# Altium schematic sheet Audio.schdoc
size 420 x 297 mm; Symbol: Drawing-Symbol_A4; Company: 嘉立创EDA; Version: V1.0; Page Size: A4; @Project Name: A113 Android MircroPhone; @Page Count: 7; @Update Date: 2025-12-04; @Create Date: 2025-12-04; @Schematic Name: Schematic1; @Page No: 6; @Page Name: Audio; @Create Time: 23:41:37; @Update Time: 23:41:46; Border: 1; Width: 1655; Height: 1170; Region Start: 1; X Region Count: 6; Y Region Count: 4; Blade Width: 10; Title Block Position: 3; @Board Name: Board1; Device: Drawing-Symbol_A4
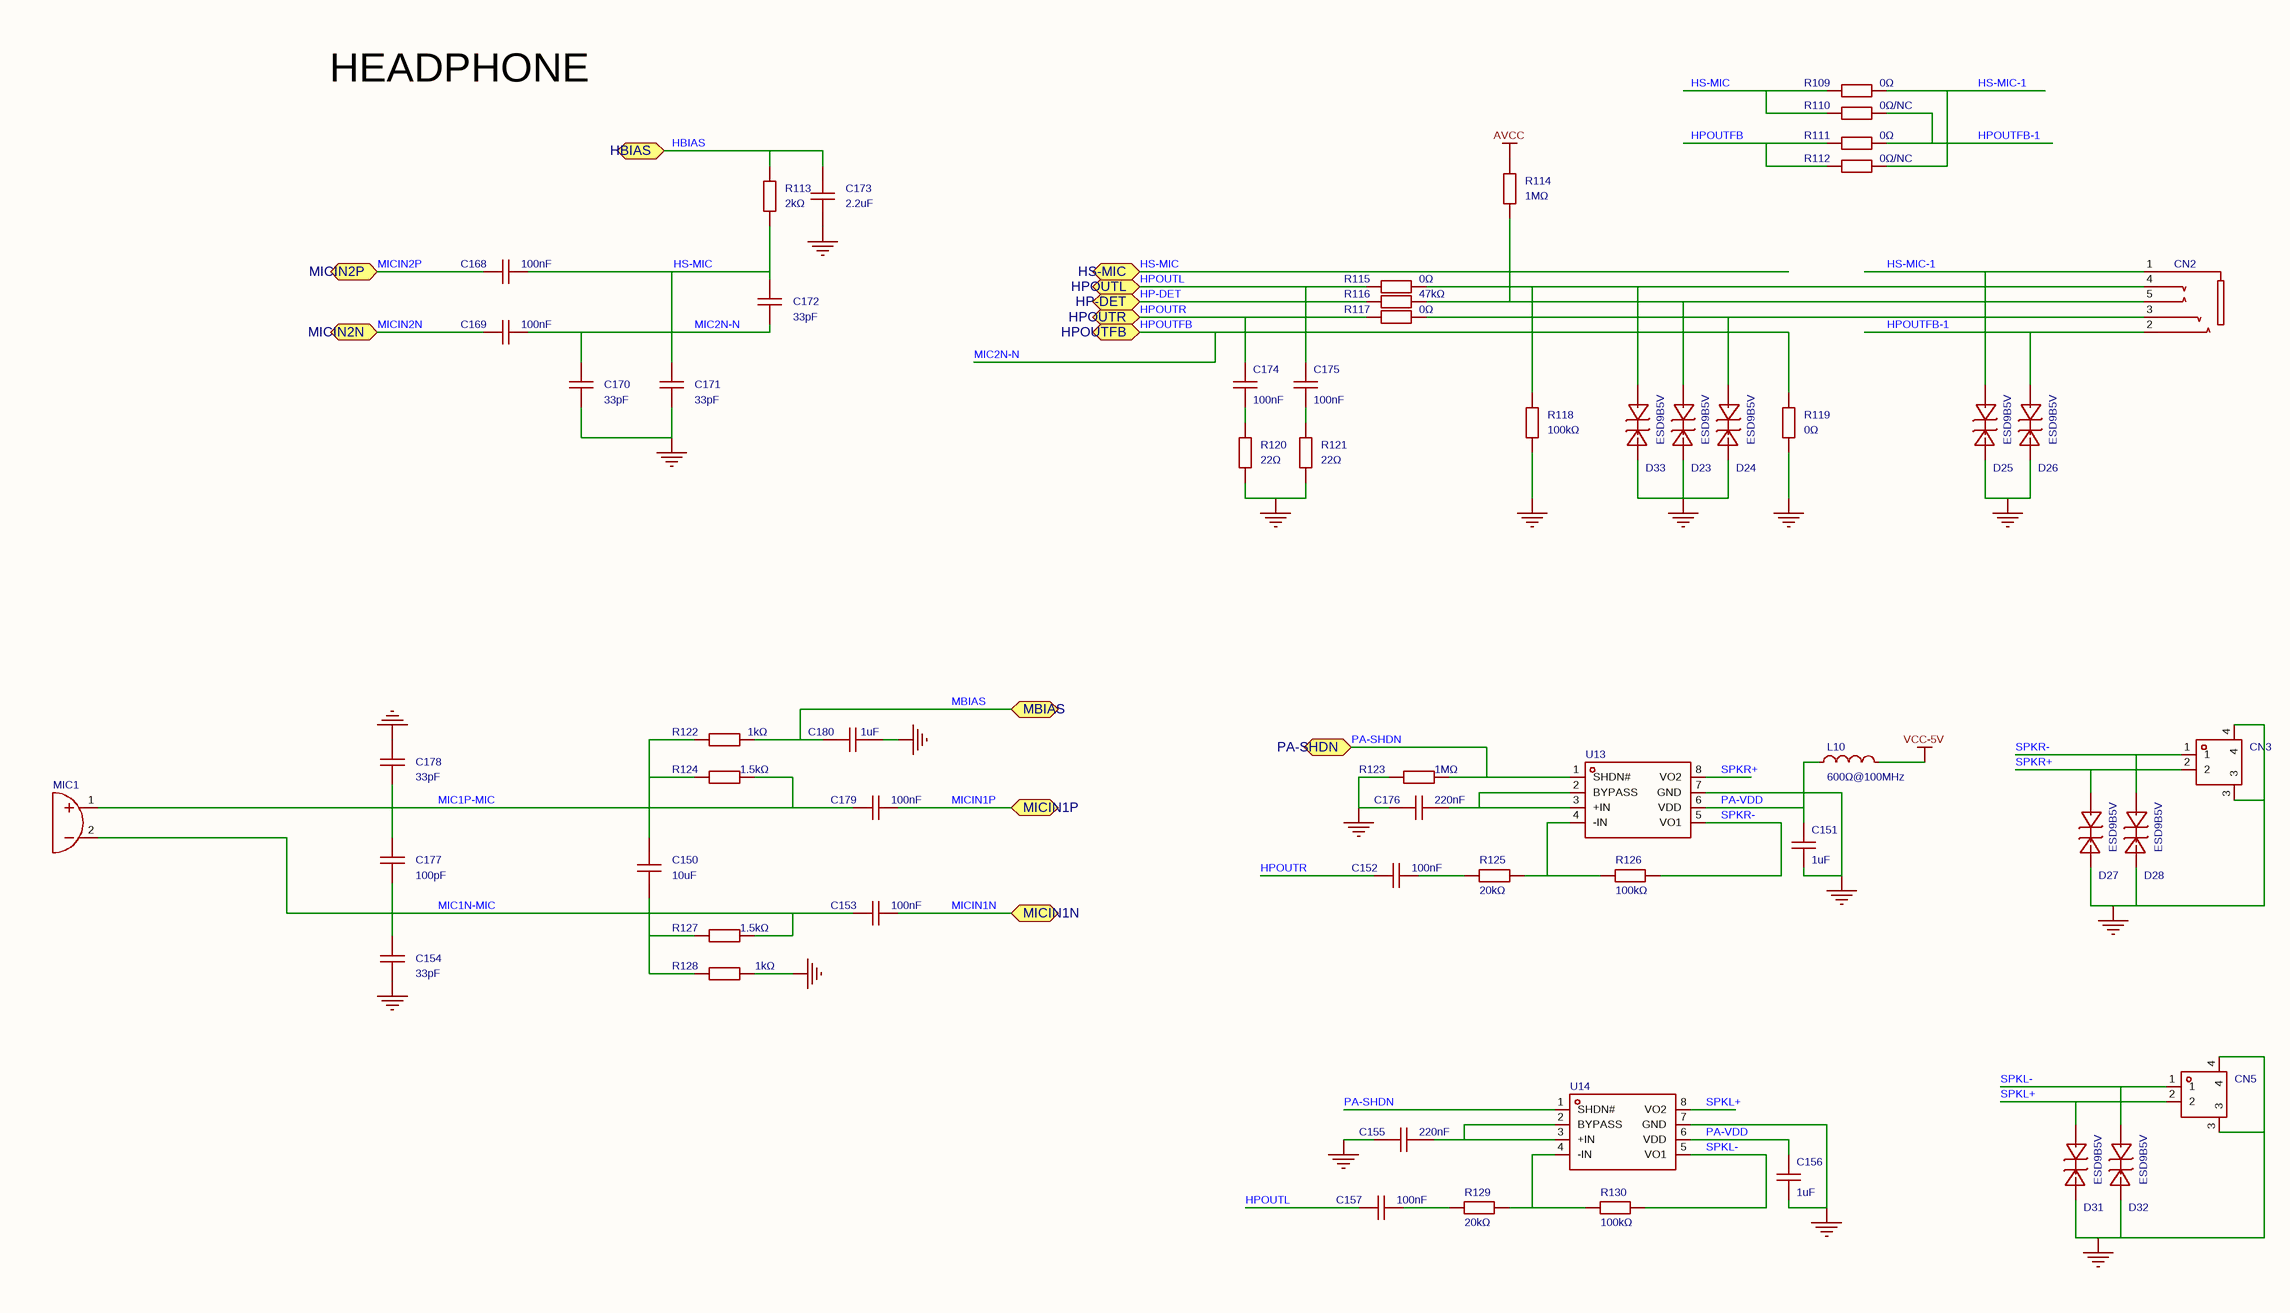
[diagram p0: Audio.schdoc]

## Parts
C150  10uF  [C0603]
C151  1uF  [C0402]
C152  100nF  [C0402]
C153  100nF  [C0402]
C154  33pF  [C0402]
C155  220nF  [C0402]
C156  1uF  [C0402]
C157  100nF  [C0402]
C168  100nF  [C0402]
C169  100nF  [C0402]
C170  33pF  [C0402]
C171  33pF  [C0402]
C172  33pF  [C0402]
C173  2.2uF  [C0402]
C174  100nF  [C0402]
C175  100nF  [C0402]
C176  220nF  [C0402]
C177  100pF  [C0402]
C178  33pF  [C0402]
C179  100nF  [C0402]
C180  1uF  [C0402]
CN2  ST-0277D00-052-142  [AUDIO-TH_ST-0277D00-052-142]  (value not drawn)
CN3  1.0-2PWB  [CONN-SMD_2P-P1.00_DEALON_1.0-2PWB]  (value not drawn)
CN5  1.0-2PWB  [CONN-SMD_2P-P1.00_DEALON_1.0-2PWB]  (value not drawn)
D23  ESD9B5V  [SOD-923_L0.8-W0.6-LS1.0-BI-1]
D24  ESD9B5V  [SOD-923_L0.8-W0.6-LS1.0-BI-1]
D25  ESD9B5V  [SOD-923_L0.8-W0.6-LS1.0-BI-1]
D26  ESD9B5V  [SOD-923_L0.8-W0.6-LS1.0-BI-1]
D27  ESD9B5V  [SOD-923_L0.8-W0.6-LS1.0-BI-1]
D28  ESD9B5V  [SOD-923_L0.8-W0.6-LS1.0-BI-1]
D31  ESD9B5V  [SOD-923_L0.8-W0.6-LS1.0-BI-1]
D32  ESD9B5V  [SOD-923_L0.8-W0.6-LS1.0-BI-1]
D33  ESD9B5V  [SOD-923_L0.8-W0.6-LS1.0-BI-1]
L10  Impedance @ Frequency: 600Ω@100MHz  [L0603]  (hidden comment: CBG160808U601T)
MIC1  GMI6027P-2C30DB  [MIC-TH_BD6.0-P1.90-D0.4-L]  (value not drawn)
R109  0Ω  [R0402]
R110  0Ω/NC  [R0402]
R111  0Ω  [R0402]
R112  0Ω/NC  [R0402]
R113  2kΩ  [R0402]
R114  1MΩ  [R0402]
R115  0Ω  [R0402]
R116  47kΩ  [R0402]
R117  0Ω  [R0402]
R118  100kΩ  [R0402]
R119  0Ω  [R0402]
R120  22Ω  [R0402]
R121  22Ω  [R0402]
R122  1kΩ  [R0402]
R123  1MΩ  [R0402]
R124  1.5kΩ  [R0402]
R125  20kΩ  [R0402]
R126  100kΩ  [R0402]
R127  1.5kΩ  [R0402]
R128  1kΩ  [R0402]
R129  20kΩ  [R0402]
R130  100kΩ  [R0402]
U13  LPA4890MSF  [MSOP-8_L3.0-W3.0-P0.65-LS5.0-BL]  (value not drawn)
U14  LPA4890MSF  [MSOP-8_L3.0-W3.0-P0.65-LS5.0-BL]  (value not drawn)

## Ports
HBIAS (bidir), HP-DET (bidir), HPOUTFB (bidir), HPOUTL (bidir), HPOUTR (bidir), HS-MIC (bidir), MBIAS (bidir), MICIN1N (bidir), MICIN1P (bidir), MICIN2N (bidir), MICIN2P (bidir), PA-SHDN (bidir)

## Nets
AVCC: R114.2
GND: C151.1 C154.1 C155.2 C156.1 C170.1 C171.1 C173.1 C176.2 C178.2 C180.2 CN3.3 CN3.4 CN5.3 CN5.4 D23.1(C) D24.1(C) D25.1(C) D26.1(C) D27.1(C) D28.1(C) D31.1(C) D32.1(C) D33.1(C) R118.1 R119.1 R120.1 R121.1 R123.2 R128.2 U13.7(GND) U14.7(GND)
VCC-5V: L10.2
HBIAS: C173.2 R113.2 ; port HBIAS
HP-DET: R116.2 ; port HP-DET
HPOUTFB: C169.1 C170.2 C172.1 R111.1 R112.1 R119.2 ; port HPOUTFB  [also labelled MIC2N-N]
HPOUTFB-1: CN2.2 D26.2(A) R110.2 R111.2
HPOUTL: C157.2 C175.1 R115.1 ; port HPOUTL
HPOUTR: C152.2 C174.1 R117.1 ; port HPOUTR
HS-MIC: C168.1 C171.2 C172.2 R109.1 R110.1 R113.1 ; port HS-MIC
HS-MIC-1: CN2.1 D25.2(A) R109.2 R112.2
MBIAS: C180.1 R122.2 ; port MBIAS
MIC1N-MIC: C153.2 C154.2 C177.1 MIC1.2 R127.2
MIC1P-MIC: C177.2 C178.1 C179.2 MIC1.1 R124.2
MICIN1N: C153.1 ; port MICIN1N
MICIN1P: C179.1 ; port MICIN1P
MICIN2N: C169.2 ; port MICIN2N
MICIN2P: C168.2 ; port MICIN2P
PA-SHDN: R123.1 U13.1(SHDN#) U14.1(SHDN#) ; port PA-SHDN
PA-VDD: C151.2 C156.2 L10.1 U13.6(VDD) U14.6(VDD)
SPKL+: CN5.2 D31.2(A) U14.8(VO2)
SPKL-: CN5.1 D32.2(A) R130.1 U14.5(VO1)
SPKR+: CN3.2 D27.2(A) U13.8(VO2)
SPKR-: CN3.1 D28.2(A) R126.1 U13.5(VO1)
NetC150_1: C150.1 R127.1 R128.1
NetC150_2: C150.2 R122.1 R124.1
NetC152_1: C152.1 R125.1
NetC155_1: C155.1 U14.2(BYPASS) U14.3(+IN)
NetC157_1: C157.1 R129.1
NetC174_2: C174.2 R120.2
NetC175_2: C175.2 R121.2
NetC176_1: C176.1 U13.2(BYPASS) U13.3(+IN)
NetCN2_3: CN2.3 D24.2(A) R117.2
NetCN2_4: CN2.4 D33.2(A) R115.2 R118.2
NetCN2_5: CN2.5 D23.2(A) R114.1 R116.1
NetR125_2: R125.2 R126.2 U13.4(-IN)
NetR129_2: R129.2 R130.2 U14.4(-IN)

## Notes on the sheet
- HEADPHONE

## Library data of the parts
C150 = CL10A106KP8NNNC: 容值:10uF;精度:±10%;额定电压:10V;材质(温度系数):X5R;; Manufacturer: SAMSUNG(三星); AddInBom: yes; ModelId: ac125912035d415993ca9572d50418b1; ModelName: C0603_L1.6-W0.8-H0.8; ModelTransform: 62.992,31.496,0,0,0,0,0,0,0; Tolerance: ±10%; Voltage Rated: 10V; Temperature Coefficient: X5R
C151 C156 = CL05A105KA5NQNC: 容值:1uF;精度:±10%;额定电压:25V;材质(温度系数):X5R;; Manufacturer: SAMSUNG(三星); Symbol: CL05A105KP5NNNC; AddInBom: yes; ModelId: 36a51122f27c49738f86b3bfa98863e0; ModelName: C0402_L1.0-W0.5-H0.5; ModelTransform: 39.37,19.685,0,0,0,0,0,0,0; Tolerance: ±10%; Voltage Rated: 25V; Temperature Coefficient: X5R
C152 C153 C157 C168 C169 C174 C175 C179 = CL05B104KO5NNNC: 容值:100nF;精度:±10%;额定电压:16V;材质(温度系数):X7R;; Manufacturer: SAMSUNG(三星); AddInBom: yes; ModelId: 36a51122f27c49738f86b3bfa98863e0; ModelName: C0402_L1.0-W0.5-H0.5; ModelTransform: 39.37,19.685,0,0,0,0,0,0,0; Tolerance: ±10%; Voltage Rated: 16V; Temperature Coefficient: X7R
C154 C170-C172 C178 = CL05C330JB5NNNC: 容值:33pF;精度:±5%;额定电压:50V;材质(温度系数):C0G;; Manufacturer: SAMSUNG(三星); AddInBom: yes; ModelId: 36a51122f27c49738f86b3bfa98863e0; ModelName: C0402_L1.0-W0.5-H0.5; ModelTransform: 39.37,19.685,0,0,0,0,0,0,0; Tolerance: ±5%; Voltage Rated: 50V; Temperature Coefficient: C0G
C155 C176 = CL05B224KP5NNNC: 容值:220nF;精度:±10%;额定电压:10V;材质(温度系数):X7R;; Manufacturer: SAMSUNG(三星); AddInBom: yes; ModelId: 36a51122f27c49738f86b3bfa98863e0; ModelName: C0402_L1.0-W0.5-H0.5; ModelTransform: 39.37,19.685,0,0,0,0,0,0,0; Tolerance: ±10%; Voltage Rated: 10V; Temperature Coefficient: X7R
C173 = CL05A225KP5NSNC: 容值:2.2uF;精度:±10%;额定电压:10V;材质(温度系数):X5R;; Manufacturer: SAMSUNG(三星); AddInBom: yes; ModelId: 36a51122f27c49738f86b3bfa98863e0; ModelName: C0402_L1.0-W0.5-H0.5; ModelTransform: 39.37,19.685,0,0,0,0,0,0,0; Tolerance: ±10%; Voltage Rated: 10V; Temperature Coefficient: X5R
C177 = CL05C101JB5NNNC: 容值:100pF;精度:±5%;额定电压:50V;材质(温度系数):C0G;; Manufacturer: SAMSUNG(三星); AddInBom: yes; ModelId: 36a51122f27c49738f86b3bfa98863e0; ModelName: C0402_L1.0-W0.5-H0.5; ModelTransform: 39.37,19.685,0,0,0,0,0,0,0; Tolerance: ±5%; Voltage Rated: 50V; Temperature Coefficient: C0G
C180 = CL05A105KP5NNNC: 容值:1uF;精度:±10%;额定电压:10V;材质(温度系数):X5R;; Manufacturer: SAMSUNG(三星); Symbol: CL05A105KA5NQNC; AddInBom: yes; ModelId: 36a51122f27c49738f86b3bfa98863e0; ModelName: C0402_L1.0-W0.5-H0.5; ModelTransform: 39.37,19.685,0,0,0,0,0,0,0; Tolerance: ±10%; Voltage Rated: 10V; Temperature Coefficient: X5R
CN2 = ST-0277D00-052-142: 连接器类型:3.5mm耳机座;额定电流:1A;额定电压:20V;触头材质:高导铜;触头镀层:镀金;工作温度范围:-20℃~+70℃;焊接温度(最大值):235℃;; Manufacturer: G-Switch(品赞); AddInBom: yes; Current Rating (Max): 1A; Voltage Rating (Max): 20V; Welding Temperature (Max): 235℃; ModelId: 496a9a1f08fd42398d8c4d3225953bba; ModelTransform: 535.432,326.771,0,0,0,0,-27.046,0.001,-78.74
CN3 CN5 = 1.0-2PWB: 参考系列:-;间距:1mm;插针结构:1x2P;排数:1;每排PIN数:2;行距:-;公母:公型插针;安装方式:卧贴;额定电流:-;工作温度范围:-25℃~+85℃;; Manufacturer: DEALON(德艺隆); AddInBom: yes; ModelId: 057f67d778f5441187ee220f82d652c8; ModelTransform: 157.48,204.724,0,0,0,0,0,-7.165,0; Pitch: 1mm; Pins Structure: 1x2P; Number of PINs Per Row: 2; Gender: 公型插针
D23-D28 D31-D33 = ESD9B5V: Manufacturer: TECH PUBLIC(台舟); AddInBom: yes; ModelId: 2f595e76c437472fa7f031dc65d7fe13; ModelTransform: 39.37,23.622,0,0,0,0,-0.005,0,0
L10 = CBG160808U601T: 标称阻抗@测试频率:600Ω@100MHz;误差:±25%;直流电阻(RDC):500mΩ;; Manufacturer: FH(风华); AddInBom: yes; ModelId: 2bc5ec593d464d6ba9807aec0b5673c2; ModelName: L0603_L1.6-W0.8-H0.5_BEAD; ModelTransform: 62.992,31.496,0,180,0,0,0.094,0.629,0; Tolerance: ±25%; DC Resistance: 500mΩ; Current Rating: 200mA; Circuits: 1
MIC1 = GMI6027P-2C30DB: Manufacturer: INGHAi(赢海); AddInBom: yes; ModelId: 14beca5542da4211ac0cab0f488bdd66; ModelTransform: 236.22,236.218,0,0,0,0,0,35.43,-118.11
R109 R111 = 0402WGF0000TCE: 电阻类型:厚膜电阻;阻值:0Ω;精度:±1%;功率:62.5mW;; Manufacturer: UNI-ROYAL(厚声); Symbol: RC0402JR-070RL; AddInBom: yes; ModelId: 671aefced39d4c318694bba8bd8efd39; ModelName: R0402_L1.0-W0.5-H0.5; ModelTransform: 39.37,19.685,0,0,0,0,0,0.0005,0; Tolerance: ±1%; Power(Watts): 62.5mW; Temperature Coefficient: ±800ppm/℃; Overload Voltage (Max): 50V
R110 R112 = RC0402JR-070RL: 电阻类型:厚膜电阻;阻值:0Ω;精度:-;功率:62.5mW;; Manufacturer: YAGEO(国巨); Standardization Check: false; AddInBom: yes; ModelId: 671aefced39d4c318694bba8bd8efd39; ModelName: R0402_L1.0-W0.5-H0.5; ModelTransform: 39.37,19.685,0,0,0,0,0,0.0005,0; Power(Watts): 62.5mW; Overload Voltage (Max): 50V
R113 = RC0402FR-072KL: 电阻类型:厚膜电阻;阻值:2kΩ;精度:±1%;功率:62.5mW;; Manufacturer: YAGEO(国巨); AddInBom: yes; ModelId: 671aefced39d4c318694bba8bd8efd39; ModelName: R0402_L1.0-W0.5-H0.5; ModelTransform: 39.37,19.685,0,0,0,0,0,0.0005,0; Tolerance: ±1%; Power(Watts): 62.5mW; Temperature Coefficient: ±100ppm/℃; Overload Voltage (Max): 50V
R114 R123 = RC0402FR-071ML: 电阻类型:厚膜电阻;阻值:1MΩ;精度:±1%;功率:62.5mW;; Manufacturer: YAGEO(国巨); AddInBom: yes; ModelId: 671aefced39d4c318694bba8bd8efd39; ModelName: R0402_L1.0-W0.5-H0.5; ModelTransform: 39.37,19.685,0,0,0,0,0,0.0005,0; Tolerance: ±1%; Power(Watts): 62.5mW; Temperature Coefficient: ±100ppm/℃; Overload Voltage (Max): 50V
R115 R117 R119 = 0402WGF0000TCE: 电阻类型:厚膜电阻;阻值:0Ω;精度:±1%;功率:62.5mW;; Manufacturer: UNI-ROYAL(厚声); Symbol: RC0402JR-070RL; Standardization Check: false; AddInBom: yes; ModelId: 671aefced39d4c318694bba8bd8efd39; ModelName: R0402_L1.0-W0.5-H0.5; ModelTransform: 39.37,19.685,0,0,0,0,0,0.0005,0; Tolerance: ±1%; Power(Watts): 62.5mW; Temperature Coefficient: ±800ppm/℃; Overload Voltage (Max): 50V
R116 = 0402WGF4702TCE: 电阻类型:厚膜电阻;阻值:47kΩ;精度:±1%;功率:62.5mW;; Manufacturer: UNI-ROYAL(厚声); AddInBom: yes; ModelId: 671aefced39d4c318694bba8bd8efd39; ModelName: R0402_L1.0-W0.5-H0.5; ModelTransform: 39.37,19.685,0,0,0,0,0,0.0005,0; Tolerance: ±1%; Power(Watts): 62.5mW; Temperature Coefficient: ±100ppm/℃; Overload Voltage (Max): 50V
R118 R126 R130 = RC0402FR-07100KL: 电阻类型:厚膜电阻;阻值:100kΩ;精度:±1%;功率:62.5mW;; Manufacturer: YAGEO(国巨); AddInBom: yes; ModelId: 671aefced39d4c318694bba8bd8efd39; ModelName: R0402_L1.0-W0.5-H0.5; ModelTransform: 39.37,19.685,0,0,0,0,0,0.0005,0; Tolerance: ±1%; Power(Watts): 62.5mW; Temperature Coefficient: ±100ppm/℃; Overload Voltage (Max): 50V
R120 R121 = RC0402FR-0722RL: 电阻类型:厚膜电阻;阻值:22Ω;精度:±1%;功率:62.5mW;; Manufacturer: YAGEO(国巨); AddInBom: yes; ModelId: 671aefced39d4c318694bba8bd8efd39; ModelName: R0402_L1.0-W0.5-H0.5; ModelTransform: 39.37,19.685,0,0,0,0,0,0.0005,0; Tolerance: ±1%; Power(Watts): 62.5mW; Temperature Coefficient: ±100ppm/℃; Overload Voltage (Max): 50V
R122 R128 = AC0402FR-071KL: 电阻类型:厚膜电阻;阻值:1kΩ;精度:±1%;功率:62.5mW;; Manufacturer: YAGEO(国巨); AddInBom: yes; ModelId: 671aefced39d4c318694bba8bd8efd39; ModelName: R0402_L1.0-W0.5-H0.5; ModelTransform: 39.37,19.685,0,0,0,0,0,0.0005,0; Tolerance: ±1%; Power(Watts): 62.5mW; Temperature Coefficient: ±100ppm/℃; Overload Voltage (Max): 50V
R124 R127 = RC0402FR-071K5L: 电阻类型:厚膜电阻;阻值:1.5kΩ;精度:±1%;功率:62.5mW;; Manufacturer: YAGEO(国巨); AddInBom: yes; ModelId: 671aefced39d4c318694bba8bd8efd39; ModelName: R0402_L1.0-W0.5-H0.5; ModelTransform: 39.37,19.685,0,0,0,0,0,0.0005,0; Tolerance: ±1%; Power(Watts): 62.5mW; Temperature Coefficient: ±100ppm/℃; Overload Voltage (Max): 50V
R125 R129 = RC0402FR-0720KL: 电阻类型:厚膜电阻;阻值:20kΩ;精度:±1%;功率:62.5mW;; Manufacturer: YAGEO(国巨); AddInBom: yes; ModelId: 671aefced39d4c318694bba8bd8efd39; ModelName: R0402_L1.0-W0.5-H0.5; ModelTransform: 39.37,19.685,0,0,0,0,0,0.0005,0; Tolerance: ±1%; Power(Watts): 62.5mW; Temperature Coefficient: ±100ppm/℃; Overload Voltage (Max): 50V
U13 U14 = LPA4890MSF: 功放类型:-;输出功率:-;; Manufacturer: LOWPOWER(微源半导体); AddInBom: yes; ModelId: bedc0aeebe0a475e87aaac88bd02a14b; ModelName: MSOP-8_L3.0-W3.0-H1.1-LS4.9-P0.65; ModelTransform: 196.85,118.11,0,90,0,0,0,0,0; Supply Voltage: 2.5V~5.5V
